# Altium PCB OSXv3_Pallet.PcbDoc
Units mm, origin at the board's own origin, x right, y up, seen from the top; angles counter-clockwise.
Board outline 56.35 x 99.69 mm, 4 copper layers (Top Layer, Mid-Layer 1, Mid-Layer 2, Bottom Layer); 0 components, 0 nets, 50 pads, 0 vias.
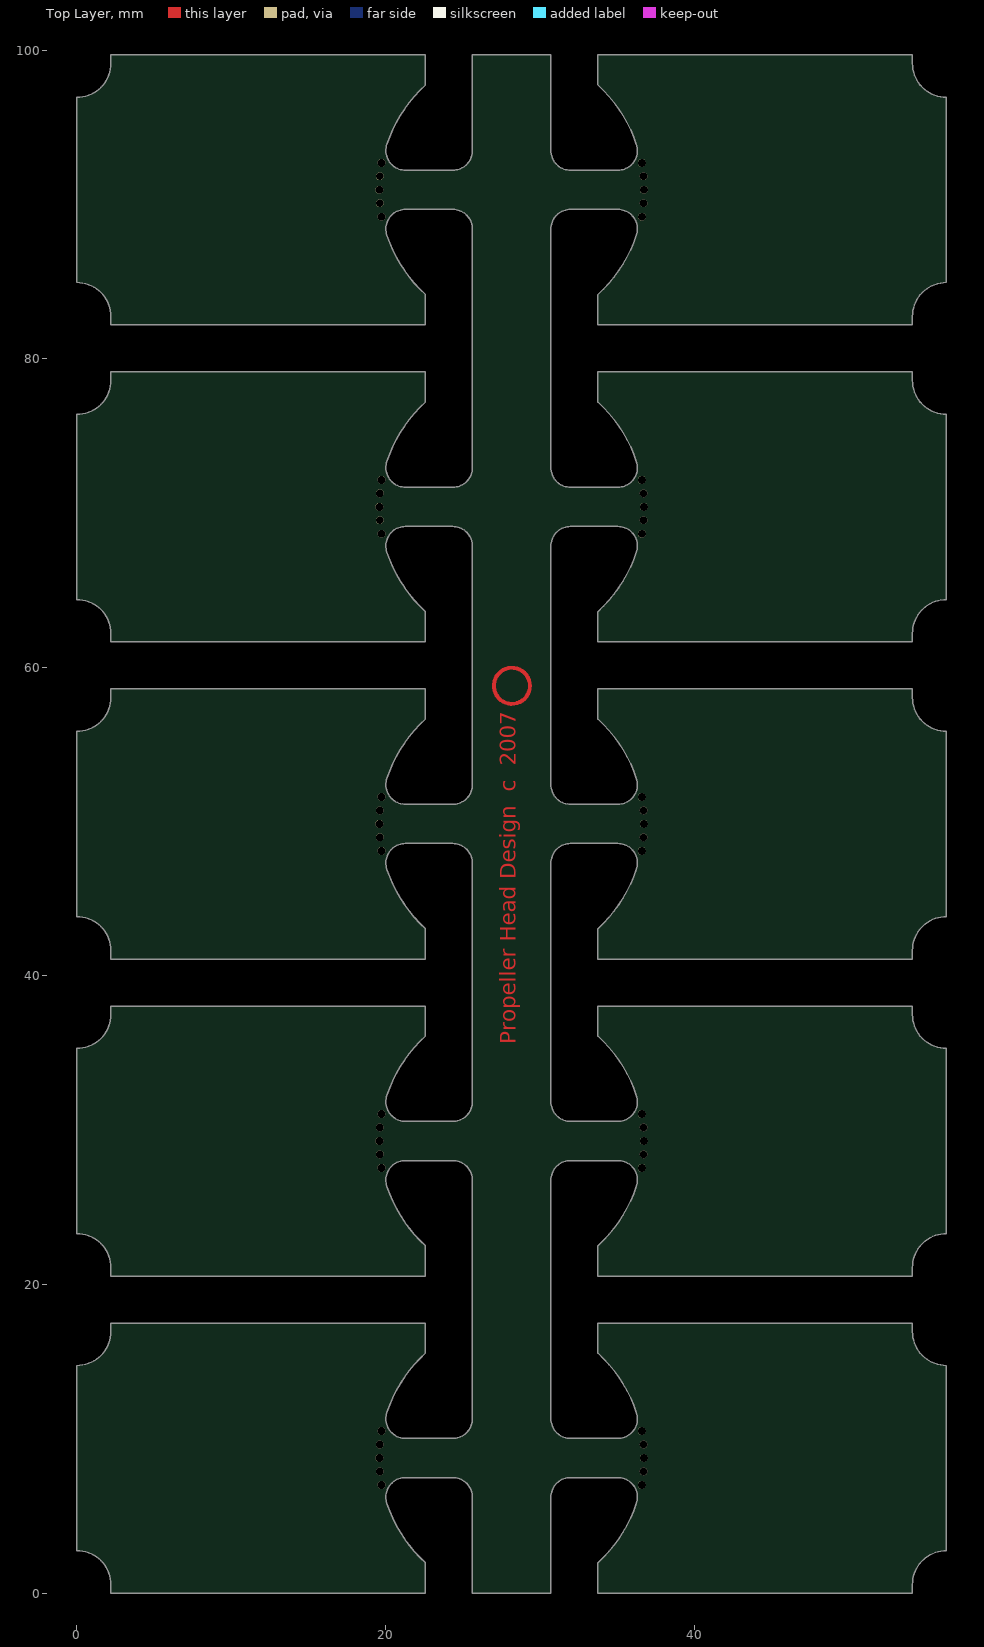
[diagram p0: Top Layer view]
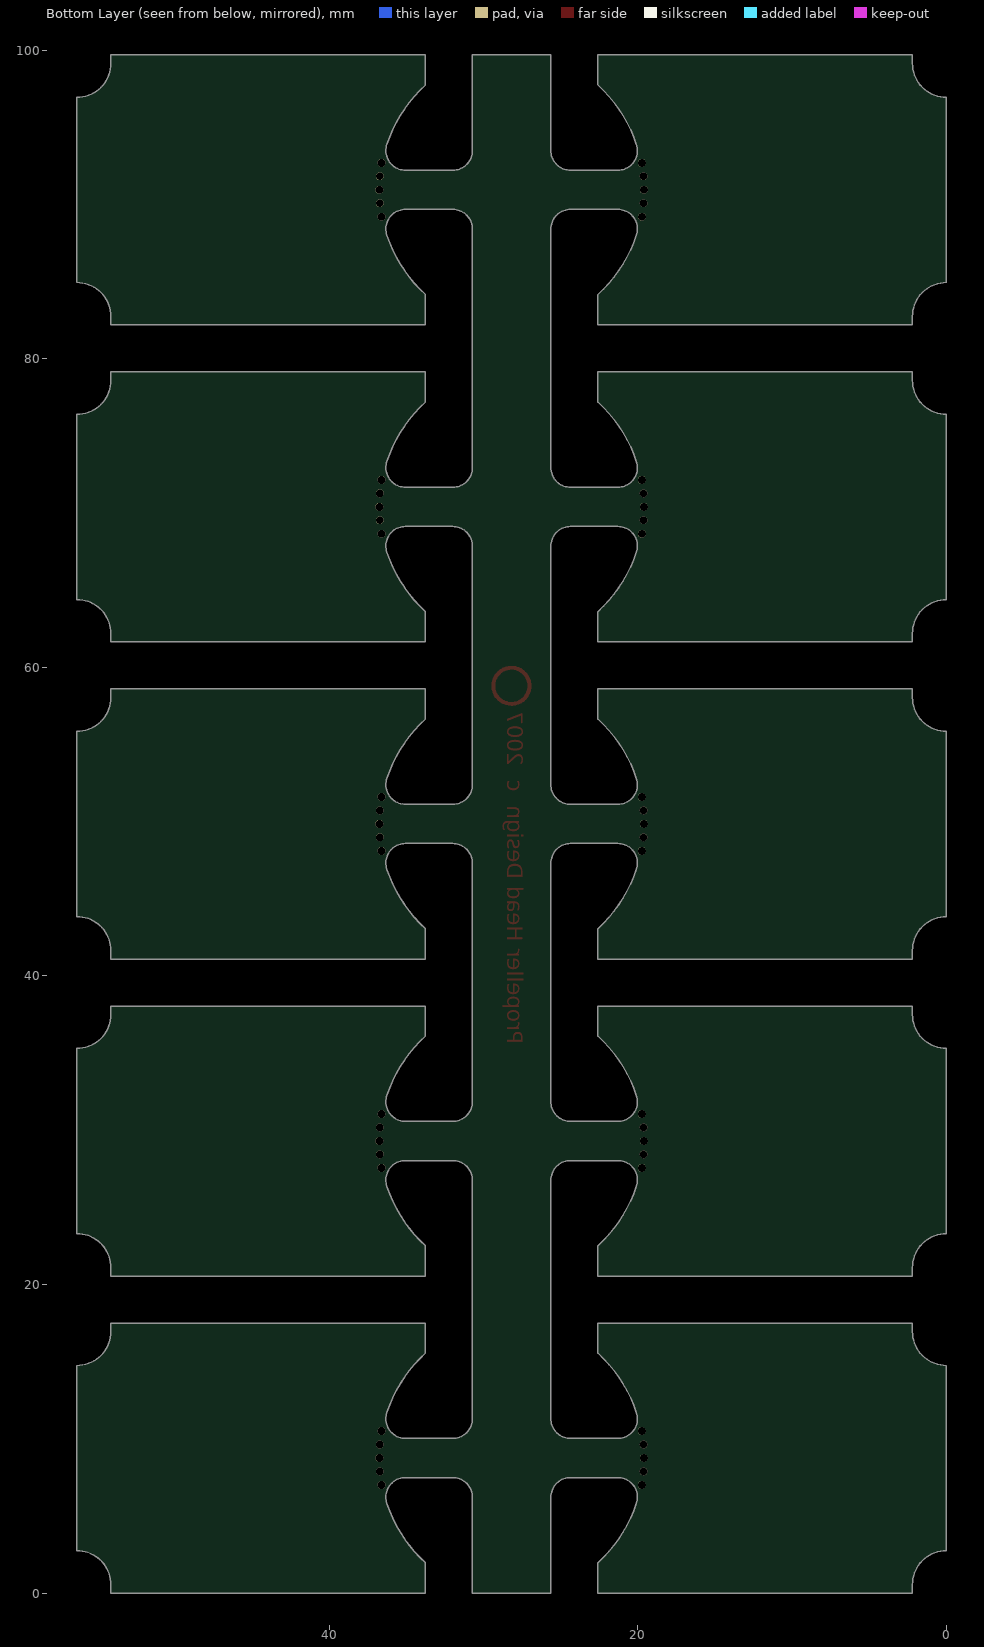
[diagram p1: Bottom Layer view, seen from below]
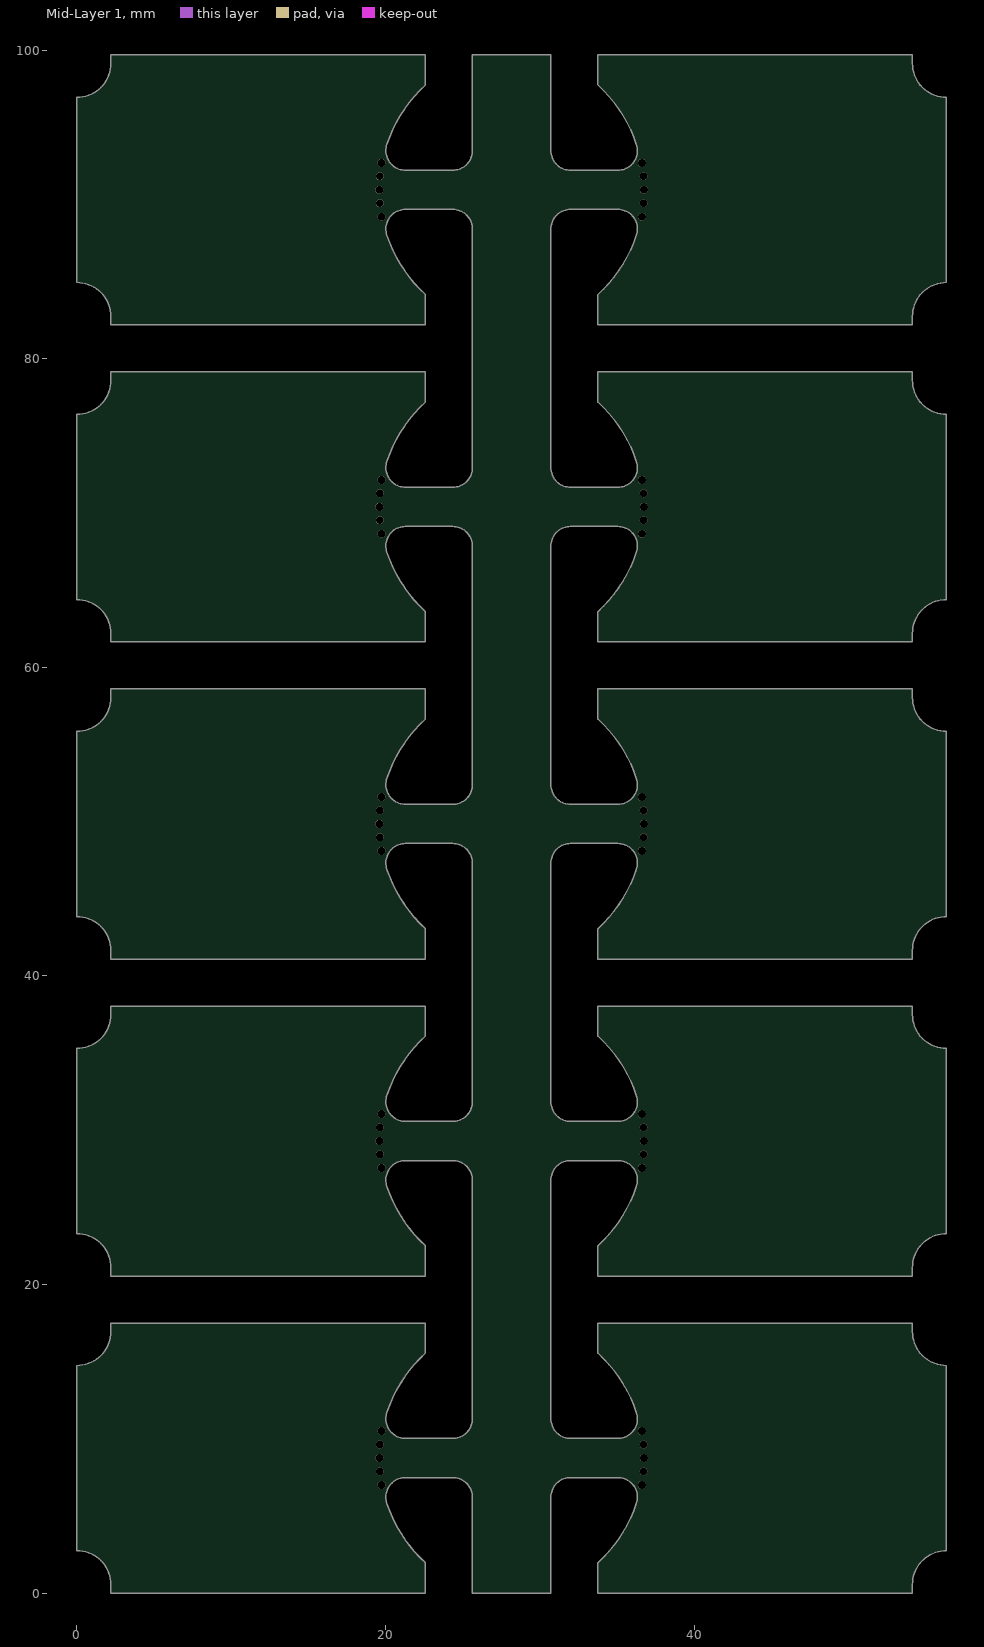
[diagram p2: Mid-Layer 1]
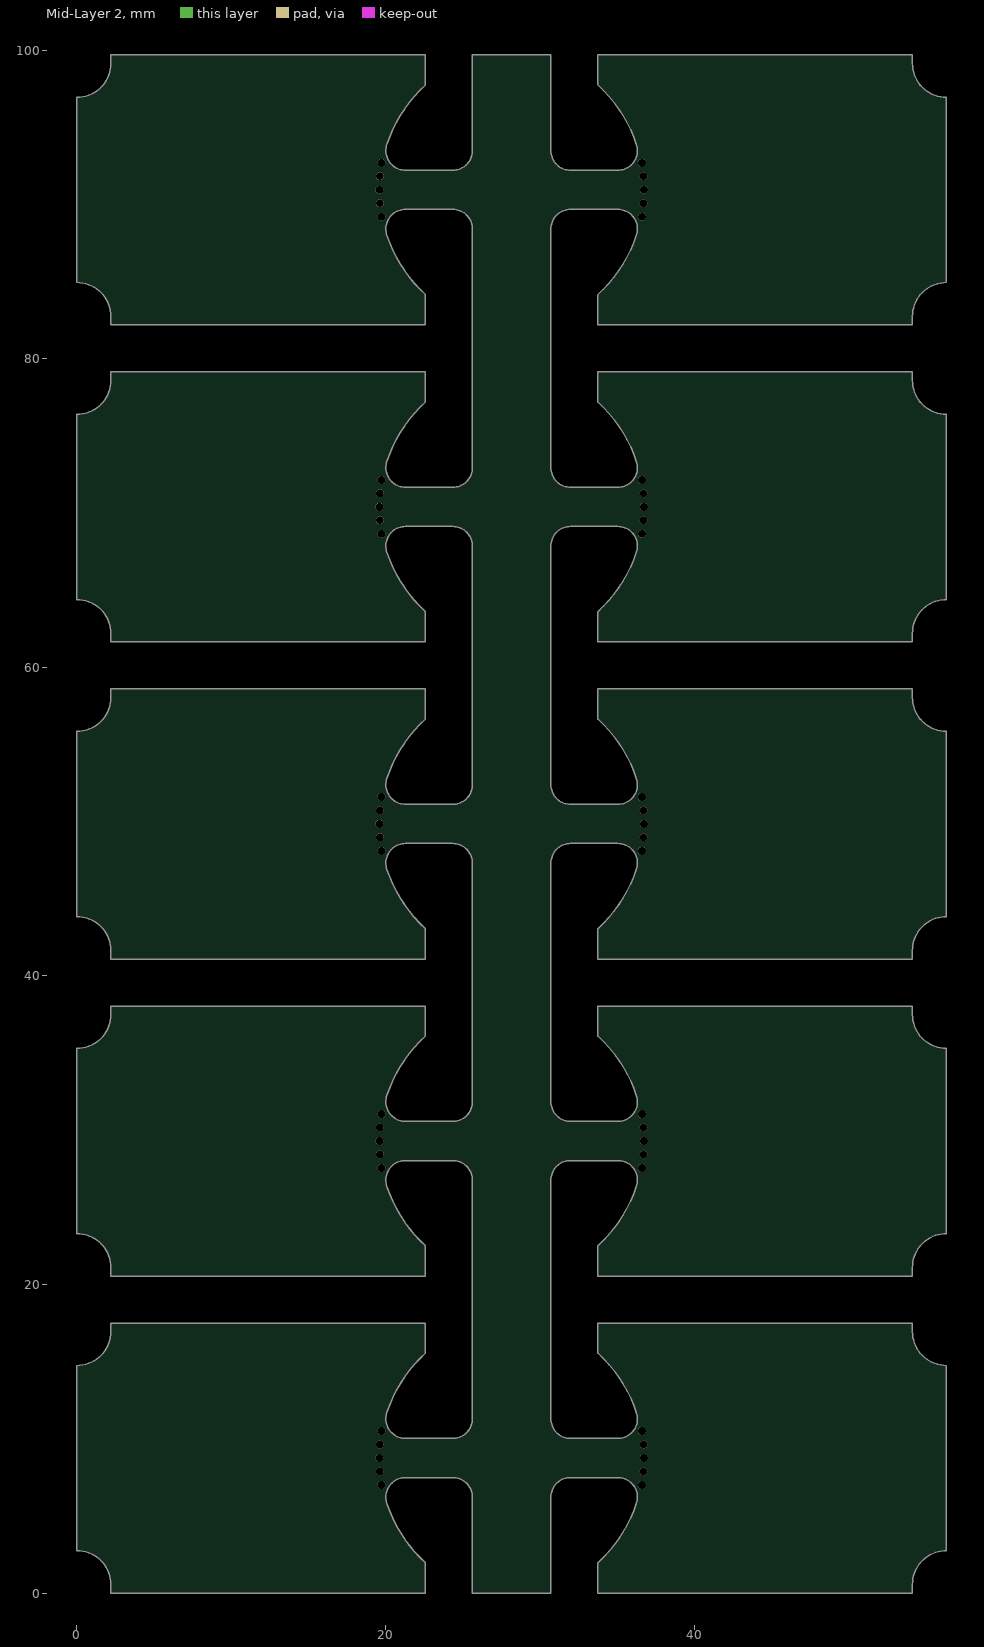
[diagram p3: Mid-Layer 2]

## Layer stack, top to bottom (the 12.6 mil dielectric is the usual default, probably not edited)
Top Layer: signal copper 0.0356
Dielectric: prepreg 0.32, FR-4, Dk 4.8
Mid-Layer 1: signal copper 0.0356
Dielectric: core 0.32, FR-4, Dk 4.8
Mid-Layer 2: signal copper 0.0356
Dielectric: prepreg 0.32, FR-4, Dk 4.8
Bottom Layer: signal copper 0.0356

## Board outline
2.2,0 2.2,0.55 ccw(c0,0.55) 0,2.75 0,14.75 ccw(c0,16.95) 2.2,16.95 2.2,17.5 22.588,17.5 22.588,15.552 ccw(c28.831,8.758) 20.086,11.703 ccw(c21.29,11.298) 20.259,10.557 ccw(c21.29,11.298) 21.29,10.028 24.363,10.028 ccw(c24.363,11.298) 25.633,11.298 25.633,26.766 ccw(c24.363,26.766) 24.363,28.036 21.29,28.036 ccw(c21.29,26.766) 20.259,27.507 ccw(c21.29,26.766) 20.086,26.36 ccw(c28.831,29.306) 22.588,22.511 22.588,20.548 2.2,20.548 2.2,21.098 ccw(c0,21.098) 0,23.298 0,35.298 ccw(c0,37.498) 2.2,37.498 2.2,38.048 22.588,38.048 22.588,36.1 ccw(c28.831,29.306) 20.086,32.251 ccw(c21.29,31.846) 20.259,31.105 ccw(c21.29,31.846) 21.29,30.576 24.363,30.576 ccw(c24.363,31.846) 25.633,31.846 25.633,47.314 ccw(c24.363,47.314) 24.363,48.584 21.29,48.584 ccw(c21.29,47.314) 20.259,48.055 ccw(c21.29,47.314) 20.086,46.908 ccw(c28.831,49.854) 22.588,43.059 22.588,41.096 2.2,41.096 2.2,41.646 ccw(c0,41.646) 0,43.846 0,55.846 ccw(c0,58.046) 2.2,58.046 2.2,58.596 22.588,58.596 22.588,56.648 ccw(c28.831,49.854) 20.086,52.799 ccw(c21.29,52.394) 20.259,51.653 ccw(c21.29,52.394) 21.29,51.124 24.363,51.124 ccw(c24.363,52.394) 25.633,52.394 25.633,67.862 ccw(c24.363,67.862) 24.363,69.132 21.29,69.132 ccw(c21.29,67.862) 20.259,68.603 ccw(c21.29,67.862) 20.086,67.456 ccw(c28.831,70.402) 22.588,63.607 22.588,61.644 2.2,61.644 2.2,62.194 ccw(c0,62.194) 0,64.394 0,76.394 ccw(c0,78.594) 2.2,78.594 2.2,79.144 22.588,79.144 22.588,77.196 ccw(c28.831,70.402) 20.086,73.347 ccw(c21.29,72.942) 20.259,72.201 ccw(c21.29,72.942) 21.29,71.672 24.363,71.672 ccw(c24.363,72.942) 25.633,72.942 25.633,88.41 ccw(c24.363,88.41) 24.363,89.68 21.29,89.68 ccw(c21.29,88.41) 20.259,89.151 ccw(c21.29,88.41) 20.086,88.004 ccw(c28.831,90.95) 22.588,84.155 22.588,82.192 2.2,82.192 2.2,82.742 ccw(c0,82.742) 0,84.942 0,96.942 ccw(c0,99.142) 2.2,99.142 2.2,99.692 22.588,99.692 22.588,97.744 ccw(c28.831,90.95) 20.086,93.895 ccw(c21.29,93.49) 20.259,92.749 ccw(c21.29,93.49) 21.29,92.22 24.363,92.22 ccw(c24.363,93.49) 25.633,93.49 25.633,99.692 30.718,99.692 30.718,93.49 ccw(c31.988,93.49) 31.988,92.22 35.062,92.22 ccw(c35.062,93.49) 36.093,92.749 ccw(c35.062,93.49) 36.265,93.895 ccw(c27.521,90.95) 33.764,97.744 33.764,99.692 54.152,99.692 54.152,99.142 ccw(c56.352,99.142) 56.352,96.942 56.352,84.942 ccw(c56.352,82.742) 54.152,82.742 54.152,82.192 33.764,82.192 33.764,84.155 ccw(c27.521,90.95) 36.265,88.004 ccw(c35.062,88.41) 36.093,89.151 ccw(c35.062,88.41) 35.062,89.68 31.988,89.68 ccw(c31.988,88.41) 30.718,88.41 30.718,72.942 ccw(c31.988,72.942) 31.988,71.672 35.062,71.672 ccw(c35.062,72.942) 36.093,72.201 ccw(c35.062,72.942) 36.265,73.347 ccw(c27.521,70.402) 33.764,77.196 33.764,79.144 54.152,79.144 54.152,78.594 ccw(c56.352,78.594) 56.352,76.394 56.352,64.394 ccw(c56.352,62.194) 54.152,62.194 54.152,61.644 33.764,61.644 33.764,63.607 ccw(c27.521,70.402) 36.265,67.456 ccw(c35.062,67.862) 36.093,68.603 ccw(c35.062,67.862) 35.062,69.132 31.988,69.132 ccw(c31.988,67.862) 30.718,67.862 30.718,52.394 ccw(c31.988,52.394) 31.988,51.124 35.062,51.124 ccw(c35.062,52.394) 36.093,51.653 ccw(c35.062,52.394) 36.265,52.799 ccw(c27.521,49.854) 33.764,56.648 33.764,58.596 54.152,58.596 54.152,58.046 ccw(c56.352,58.046) 56.352,55.846 56.352,43.846 ccw(c56.352,41.646) 54.152,41.646 54.152,41.096 33.764,41.096 33.764,43.059 ccw(c27.521,49.854) 36.265,46.908 ccw(c35.062,47.314) 36.093,48.055 ccw(c35.062,47.314) 35.062,48.584 31.988,48.584 ccw(c31.988,47.314) 30.718,47.314 30.718,31.846 ccw(c31.988,31.846) 31.988,30.576 35.062,30.576 ccw(c35.062,31.846) 36.093,31.105 ccw(c35.062,31.846) 36.265,32.251 ccw(c27.521,29.306) 33.764,36.1 33.764,38.048 54.152,38.048 54.152,37.498 ccw(c56.352,37.498) 56.352,35.298 56.352,23.298 ccw(c56.352,21.098) 54.152,21.098 54.152,20.548 33.764,20.548 33.764,22.511 ccw(c27.521,29.306) 36.265,26.36 ccw(c35.062,26.766) 36.093,27.507 ccw(c35.062,26.766) 35.062,28.036 31.988,28.036 ccw(c31.988,26.766) 30.718,26.766 30.718,11.298 ccw(c31.988,11.298) 31.988,10.028 35.062,10.028 ccw(c35.062,11.298) 36.093,10.557 ccw(c35.062,11.298) 36.265,11.703 ccw(c27.521,8.758) 33.764,15.552 33.764,17.5 54.152,17.5 54.152,16.95 ccw(c56.352,16.95) 56.352,14.75 56.352,2.75 ccw(c56.352,0.55) 54.152,0.55 54.152,0 33.764,0 33.764,1.963 ccw(c27.521,8.758) 36.265,5.812 ccw(c35.062,6.218) 36.093,6.959 ccw(c35.062,6.218) 35.062,7.488 31.988,7.488 ccw(c31.988,6.218) 30.718,6.218 30.718,0 25.633,0 25.633,6.218 ccw(c24.363,6.218) 24.363,7.488 21.29,7.488 ccw(c21.29,6.218) 20.259,6.959 ccw(c21.29,6.218) 20.086,5.812 ccw(c28.831,8.758) 22.588,1.963 22.588,0

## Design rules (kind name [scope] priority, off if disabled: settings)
Clearance [All] p1: gap=0.254
ComponentClearance [All] p1: gap=0.254 collisioncheckmode=3 verticalgap=0.254
PolygonConnect [All] p1: connectstyle=Relief reliefconductorwidth=0.254 reliefentries=4 polygonreliefangle="90 Angle"
RoutingVias [All] p1: holewidth=0.711 width=1.27 viastyle="Through Hole" minholewidth=0.711 minwidth=1.27 maxholewidth=0.711 maxwidth=1.27
SolderMaskExpansion [All] p1: expansion=0.102
TestPointUsage [All] p1: valid=0 allowmultiple=FALSE
Testpoint [All] p1: side=15 testpointundercomponent=TRUE minsize=1.016 maxsize=2.54 preferedsize=1.524 minholesize=0 maxholesize=1.016 preferedholesize=0.813 testpointgrid=0.025 style=1023 order=0123456789
Width [All] p1: maxlimit=0.254 minlimit=0.254 preferedwidth=0.254
18 further rules are at their usual default settings.

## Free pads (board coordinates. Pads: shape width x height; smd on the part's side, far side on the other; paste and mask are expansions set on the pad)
  round 0.508 hole 0.508 unplated paste-5.08: 0(19.604,90.95) 0(19.626,30.179) 0(19.626,69.528) 0(19.738,10.504) 0(36.614,10.504) 0(36.726,71.275) 0(36.726,90.076) 0(36.748,49.854) 1(19.604,70.402) 1(19.626,9.631) 1(19.626,28.432) 1(19.738,48.107) 1(36.614,7.011) 1(36.614,31.052) 1(36.726,91.823) 1(36.748,70.402) 2(19.604,29.306) 2(19.626,7.884) 2(19.738,51.6) 2(19.738,89.203) 2(36.614,27.559) 2(36.614,51.6) 2(36.726,7.884) 2(36.748,90.95) 3(19.604,8.758) 3(19.626,50.727) 3(19.738,68.655) 3(19.738,92.696) 3(36.614,48.107) 3(36.614,72.148) 3(36.726,9.631) 3(36.726,28.432) 4(19.626,48.98) 4(19.626,91.823) 4(19.738,27.559) 4(19.738,72.148) 4(36.614,68.655) 4(36.614,92.696) 4(36.726,30.179) 4(36.726,48.98) 4(36.748,8.758) 5(19.604,49.854) 5(19.626,71.275) 5(19.626,90.076) 5(19.738,7.011) 5(19.738,31.052) 5(36.614,89.203) 5(36.726,50.727) 5(36.726,69.528) 5(36.748,29.306)

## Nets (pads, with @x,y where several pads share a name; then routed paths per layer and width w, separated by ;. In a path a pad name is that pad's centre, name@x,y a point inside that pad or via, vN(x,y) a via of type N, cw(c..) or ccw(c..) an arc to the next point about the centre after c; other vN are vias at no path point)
copper on no net: | length 7.4
  Top Layer w0.254: 29.365,58.801 ccw(c28.194,58.801) 29.365,58.801

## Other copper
Top Layer:
  text "Propeller Head Design  c  2007" at 28.448,35.56 h1.02 r90
  text ".GTL" at 104.488,-39.115 h2.29
  text ".LAYER_NAME" at 57.498,-39.369 h2.29
Mid-Layer 1:
  text ".G1" at 104.488,-39.115 h2.29
  text ".LAYER_NAME" at 57.498,-39.369 h2.29
Mid-Layer 2:
  text ".G2" at 104.488,-39.115 h2.29
  text ".LAYER_NAME" at 57.498,-39.369 h2.29
Bottom Layer:
  text ".GBL" at 104.488,-39.115 h2.29
  text ".LAYER_NAME" at 57.498,-39.369 h2.29

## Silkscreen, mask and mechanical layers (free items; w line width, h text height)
Top Overlay:
  text ".GTO" at 104.488,-39.115 h2.29
  text ".LAYER_NAME" at 57.498,-39.369 h2.29
Bottom Overlay:
  text ".GBO" at 104.488,-39.116 h2.29
  text ".LAYER_NAME" at 57.625,-39.242 h2.29
Top Paste:
  text ".GTP" at 104.521,-39.116 h2.29
  text ".LAYER_NAME" at 57.498,-39.369 h2.29
Bottom Paste:
  text ".GBP" at 104.521,-39.116 h2.29
  text ".LAYER_NAME" at 57.531,-39.37 h2.29
Top Solder:
  text ".GTS" at 104.488,-39.115 h2.29
  text ".LAYER_NAME" at 57.498,-39.369 h2.29
Bottom Solder:
  text ".GBS" at 104.488,-39.115 h2.29
  text ".LAYER_NAME" at 57.498,-39.369 h2.29
Mechanical 1:
  drawing of 264 lines, arcs and shapes, not listed
Mechanical 3:
  drawing of 204 lines, arcs and shapes, not listed
  text ".GM3" at 104.488,-39.115 h2.29
  text ".LAYER_NAME" at 57.498,-39.369 h2.29
Mechanical 4:
  drawing of 478 lines, arcs and shapes, not listed
  text "150" at -25.575,108.646 h2.29
  text "140" at -25.575,98.646 h2.29
  text "130" at -25.575,88.646 h2.29
  text "120" at -25.575,78.646 h2.29
  text "110" at -25.575,68.646 h2.29
  text "100" at -25.575,58.646 h2.29
  text "90" at -24.575,48.646 h2.29
  text "80" at -24.575,38.646 h2.29
  text "70" at -24.575,28.646 h2.29
  text "60" at -24.575,18.646 h2.29
  text "50" at -24.575,8.646 h2.29
  text "40" at -24.575,-1.354 h2.29
  text "30" at -24.575,-11.354 h2.29
  text "by Propeller Head Design" at 23.775,-13.332 h1.52
  text "TITLE:" at 27.283,-18.58 h1.14
  text "ENGINEER:" at 4.74,-18.932 h1.14
  text "Cliff" at 13.373,-18.916 h1.52
  text "c  2007" at 86.101,-18.928 h1.52
  text "PHONE:" at 4.84,-21.322 h1.14
  text "20" at -24.575,-21.354 h2.29
  text "OpenServo PCB" at 34.323,-22.238 h2.29
  text "408.378.1319" at 5.843,-23.719 h1.52
  text "ENGINEER:" at 4.74,-28.549 h1.14
  text "PHONE:" at 4.776,-30.577 h1.14
  text "PART NO.:" at 27.6,-30.645 h1.14
  text "REV:" at 71.733,-30.645 h1.14
  text "DATE:" at 83.48,-30.645 h1.14
  text "10" at -24.575,-31.354 h2.29
  text ".PRINT_DATE" at 89.195,-32.296 h2.29
  text "X3" at 74.422,-33.401 h2.29
  text "FILE NAME:" at 4.74,-37.693 h1.14
  text "LAYER:" at 51.476,-37.693 h1.14
  text "GERBER:" at 97.704,-37.693 h1.14
  text ".Pcb_File_Name_No_Path" at 14.9,-39.217 h1.78
  text "0" at -22.192,-42.764 h2.29
  text "Y" at -15.525,-44.987 h2.29 r270
  text "X" at -11.397,-50.384 h2.29
  text "10" at 3.425,-55.354 h2.29 r270
  text "20" at 13.425,-55.354 h2.29 r270
  text "30" at 23.425,-55.354 h2.29 r270
  text "40" at 33.425,-55.354 h2.29 r270
  text "50" at 43.425,-55.354 h2.29 r270
  text "60" at 53.425,-55.354 h2.29 r270
  text "70" at 63.425,-55.354 h2.29 r270
  text "80" at 73.425,-55.354 h2.29 r270
  text "90" at 83.425,-55.354 h2.29 r270
  text "0" at -7.905,-55.464 h2.29 r270
  text "100" at 93.425,-56.354 h2.29 r270
  text "110" at 103.425,-56.354 h2.29 r270
  text "120" at 113.425,-56.354 h2.29 r270
  text "130" at 123.425,-56.354 h2.29 r270
  text "140" at 133.425,-56.354 h2.29 r270
  text "150" at 143.425,-56.354 h2.29 r270
Drill Drawing:
  text ".Legend" at 70.485,-3.048 h1.52
  text "Drill Chart" at 70.231,-6.477 h1.52
  text ".GD1" at 104.488,-39.115 h2.29
  text ".LAYER_NAME" at 57.498,-39.369 h2.29

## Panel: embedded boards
"OS3v3.PcbDoc" at 33.764,0, 1 rows x 1 columns, spacing 63.5 x 38.1, rotation 0
"OS3v3.PcbDoc" at 33.764,20.548, 1 rows x 1 columns, spacing 63.5 x 38.1, rotation 0
"OS3v3.PcbDoc" at 33.764,41.096, 1 rows x 1 columns, spacing 63.5 x 38.1, rotation 0
"OS3v3.PcbDoc" at 33.764,61.644, 1 rows x 1 columns, spacing 63.5 x 38.1, rotation 0
"OS3v3.PcbDoc" at 33.764,82.192, 1 rows x 1 columns, spacing 63.5 x 38.1, rotation 0
"OS3v3.PcbDoc" at 22.588,99.692, 1 rows x 1 columns, spacing 63.5 x 38.1, rotation 180
"OS3v3.PcbDoc" at 22.588,79.144, 1 rows x 1 columns, spacing 63.5 x 38.1, rotation 180
"OS3v3.PcbDoc" at 22.588,58.596, 1 rows x 1 columns, spacing 63.5 x 38.1, rotation 180
"OS3v3.PcbDoc" at 22.588,38.048, 1 rows x 1 columns, spacing 63.5 x 38.1, rotation 180
"OS3v3.PcbDoc" at 22.588,17.5, 1 rows x 1 columns, spacing 63.5 x 38.1, rotation 180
